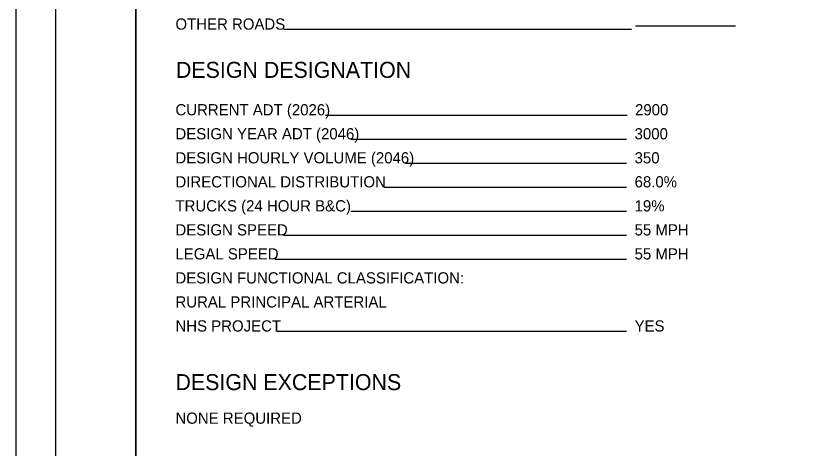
# Model space of a CAD drawing. Extents: x 6.3 to 40.3, y 9 to 31.
# Drawn here: x 6.34 to 16.34, y 14.68 to 20.09 of the extents above; entities that cross this region are included whole.
import ezdxf

# ---------------------------------------------------------------- set-up
doc = ezdxf.new("R2010")
doc.units = 0
for name, color, linetype in [('SH_Border', 7, 'Continuous'), ('SH_Cut_Line', 7, 'Continuous'), ('SH_Data', 7, 'Continuous'), ('SH_Text', 7, 'Continuous')]:
    doc.layers.add(name, color=color, linetype=linetype)

msp = doc.modelspace()

# ---------------------------------------------------------------- linework, layer by layer
at = {"layer": 'SH_Border'}
for points in [[(6.8446, 30.5457), (7.8446, 30.5457), (7.8446, 9.5457), (6.8446, 9.5457)], [(7.8446, 30.5457), (39.8446, 30.5457), (39.8446, 9.5457), (7.8446, 9.5457)]]:
    msp.add_lwpolyline(points, close=True, dxfattribs=at)
at = {"layer": 'SH_Cut_Line'}
msp.add_lwpolyline([(6.3446, 9.0457), (40.3446, 9.0457), (40.3446, 31.0457), (6.3446, 31.0457)], close=True, dxfattribs=at)
at = {"layer": 'SH_Data'}
for p, q in [((14.0446, 19.9224), (9.6917, 19.9224)), ((15.3446, 19.968), (14.0946, 19.968)), ((13.987, 18.852), (10.2156, 18.852)), ((13.9814, 18.552), (10.5331, 18.552)), ((13.9814, 18.252), (11.2169, 18.252)), ((13.9814, 17.952), (10.9483, 17.952)), ((13.9814, 17.652), (10.5331, 17.652)), ((13.9814, 17.352), (9.6906, 17.352)), ((13.9814, 17.052), (9.5868, 17.052)), ((13.9814, 16.152), (9.6115, 16.152))]:
    msp.add_line(p, q, dxfattribs=at)

# ---------------------------------------------------------------- texts
msp.add_text('DESIGN DESIGNATION', height=0.2, dxfattribs=at).set_placement((8.3446, 19.3204))
at = {"layer": 'SH_Text'}
for s, height, p in [('OTHER ROADS', 0.14, (8.339, 19.9224)), ('CURRENT ADT (2026)', 0.14, (8.339, 18.852)), ('2900', 0.14, (14.087, 18.852)), ('DESIGN YEAR ADT (2046)', 0.14, (8.339, 18.552)), ('3000', 0.14, (14.0814, 18.552)), ('DESIGN HOURLY VOLUME (2046)', 0.14, (8.339, 18.252)), ('350', 0.14, (14.0814, 18.252)), ('DIRECTIONAL DISTRIBUTION', 0.14, (8.339, 17.952)), ('68.0%', 0.14, (14.0814, 17.952)), ('TRUCKS (24 HOUR B&C)', 0.14, (8.339, 17.652)), ('19%', 0.14, (14.0814, 17.652)), ('DESIGN SPEED', 0.14, (8.339, 17.352)), ('55 MPH', 0.14, (14.0814, 17.352)), ('LEGAL SPEED', 0.14, (8.339, 17.052)), ('55 MPH', 0.14, (14.0814, 17.052)), ('DESIGN FUNCTIONAL CLASSIFICATION:', 0.14, (8.339, 16.752)), ('RURAL PRINCIPAL ARTERIAL', 0.14, (8.339, 16.452)), ('NHS PROJECT', 0.14, (8.339, 16.152)), ('YES', 0.14, (14.0814, 16.152)), ('DESIGN EXCEPTIONS', 0.2, (8.339, 15.4201)), ('NONE REQUIRED', 0.14, (8.339, 15.0001))]:
    msp.add_text(s, height=height, dxfattribs=at).set_placement(p)

doc.saveas('drawing.dxf')
